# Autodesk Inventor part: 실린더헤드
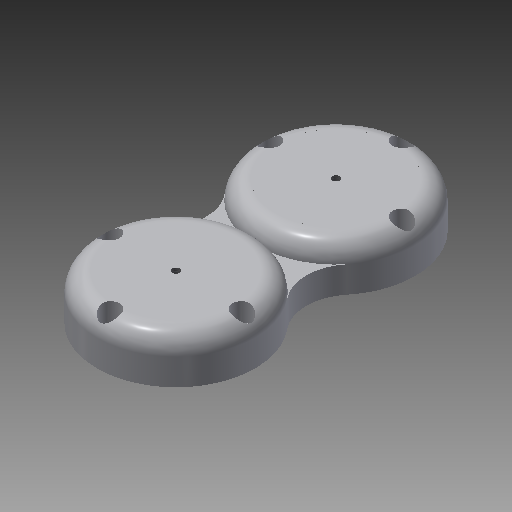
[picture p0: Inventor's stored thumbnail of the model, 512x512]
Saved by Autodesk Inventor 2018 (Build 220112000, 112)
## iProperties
Created: 2016-11
Part Number: 실린더헤드
Material: 알루미늄 6061
Document SubType Name: Modeling
Designer: mduedu
Density: 2.71 g/cm^3
Mass: 538.448 g
Surface Area: 423.673 cm^2
Volume: 198.689 cm^3
Appearance: 알루미늄 - 평지
Author: mduedu
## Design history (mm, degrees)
sketch "스케치1"
  geometry: C1 r 42 at (0, 0); 1 further point
  constraints: 1 centre point, 1 coincident
  dimensions: "d0" = 84 diameter of C1
extrude "돌출1" new body sketch "스케치1" distance "d1" = 24; taper "d2" = 0 deg
fillet "모깎기1" dims "d3" = 10
sketch "스케치2"
  geometry: C1 r 30 at (0, 0); 1 further point
  constraints: 1 centre point, 1 coincident
  dimensions: "d4" = 60 diameter of C1
extrude "돌출2" join sketch "스케치2" distance "d5" = 5; taper "d6" = 0 deg
sketch "스케치3"
  geometry: C1 r 25 at (0, 0); 1 further point
  constraints: 1 centre point, 1 coincident
  dimensions: "d7" = 50 diameter of C1
extrude "돌출3" cut sketch "스케치3" distance "d8" = 20; taper "d9" = 0 deg
hole "구멍1" diameter "d12" = 4.134; stored, may be unused: countersink angle "d16" = 90 deg, drill point angle "d18" = 118 deg; dims "d10" = 10, "d11" = 10, "d13" = 6, "d14" = 4, "d15" = 2, "d17" = 8
chamfer "모따기1" distance "d19" = 1; stored, may be unused: second distance "d20" = 2, angle "d21" = 45 deg
fillet "모깎기2" dims "d22" = 3
sketch "스케치4"
  geometry: C1 r 17.5 at (0, 0); 1 further point
  constraints: 1 centre point, 1 coincident
  dimensions: "d23" = 35 diameter of C1
extrude "돌출4" cut sketch "스케치4" distance "d24" = 2; taper "d25" = 0 deg
fillet "모깎기3" dims "d26" = 0.5
sketch "스케치5" dims "d32" = 70
  geometry: C1 r 5 at (0, 35); 3 further points
  constraints: 2 coincident, 2 vertical alignment, 1 centre point, 2 other
  dimensions: "d33" = 10 diameter of C1
extrude "돌출5" cut sketch "스케치5" distance "d34" = 10; taper "d35" = 0 deg
sketch "스케치6"
  geometry: A1 r 35 centre (0, -35) between (0, 0) and (-35, -35); 2 further points
  constraints: 3 point on circle, 2 horizontal alignment, 1 centre point, 1 coincident, 1 vertical alignment
  dimensions: "d39" = 70 diameter of A1
hole "구멍3" sketch "스케치6" at (0, 0), (-35, -35), (35, -35) diameter "d57" = 5.5; stored, may be unused: countersink angle "d61" = 90 deg, drill point angle "d63" = 118 deg; dims "d58" = 6, "d59" = 4, "d60" = 2, "d62" = 8
chamfer "모따기2" distance "d54" = 5; stored, may be unused: second distance "d55" = 2, angle "d56" = 30 deg
node "작업 평면1"
sketch "스케치8"
  geometry: L1 (0, 85)-(0, 0); A1 r 42 centre (0, 85) between (-32.469, 58.358) and (32.469, 58.358) reference; A2 r 42 centre (0, 0) between (-32.469, 26.642) and (32.469, 26.642) reference; A3 r 25 centre (51.795, 42.5) between (32.469, 26.642) and (32.469, 58.358); A4 r 25 centre (-51.795, 42.5) between (-32.469, 58.358) and (-32.469, 26.642); A5 r 25 centre (-51.795, 42.5) between (-32.469, 26.642) and (-32.469, 58.358); A6 r 25 centre (51.795, 42.5) between (32.469, 58.358) and (32.469, 26.642); A7 r 42 centre (0, 85) between (-32.469, 58.358) and (32.469, 58.358); A8 r 42 centre (0, 0) between (32.469, 26.642) and (-32.469, 26.642); 1 further point
  constraints: 16 point on circle, 6 centre point, 2 coincident, 2 end point, 2 tangent, 1 symmetric about line, 1 vertical, 1 other
  dimensions: "d65" = 50 diameter of A3
extrude "돌출6" join sketch "스케치8" distance "d67" = 14; taper "d68" = 0 deg
node "솔리드1"
pattern_circular "원형 패턴1" dims angle "d37" = 360 deg
mirror "대칭1"
other parameters: "d64" = 42.5
